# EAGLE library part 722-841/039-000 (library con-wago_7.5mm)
Serie 722, Federleiste mit Verriegelungsklinken / Series 722, Female connector with locking levers Polzahl / Pole No.: 11 Farbe / Color: lichtgrau / light gray Stand: 01.01.2012. Die jeweils aktuellen Daten zu diesem Artikel finden Sie in unserem Produktkatalog, den Sie unter www.wago.com einsehen können. As of: 01/01/2012. Please find the newest data for this article in our product catalogue, which can be viewed under www.wago.com.
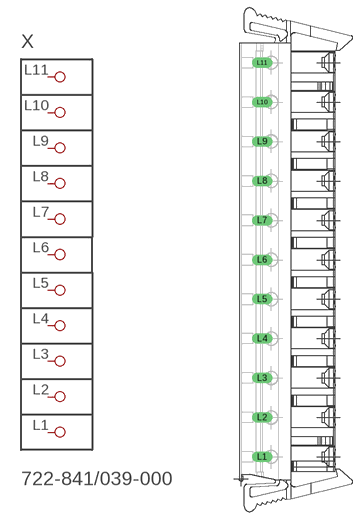
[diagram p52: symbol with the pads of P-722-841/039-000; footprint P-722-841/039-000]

Designator prefix X

## 722-841/039-000  [P-722-841/039-000]
L1  P1
L2  P2
L3  P3
L4  P4
L5  P5
L6  P6
L7  P7
L8  P8
L9  P9
L10  P10
L11  P11

## Footprint P-722-841/039-000 (pad centres in mm)
drill 1.3 long: L1 -5.909,-37.5; L2 -5.909,-30; L3 -5.909,-22.5; L4 -5.909,-15; L5 -5.909,-7.5; L6 -5.909,0; L7 -5.909,7.5; L8 -5.909,15; L9 -5.909,22.5; L10 -5.909,30; L11 -5.909,37.5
